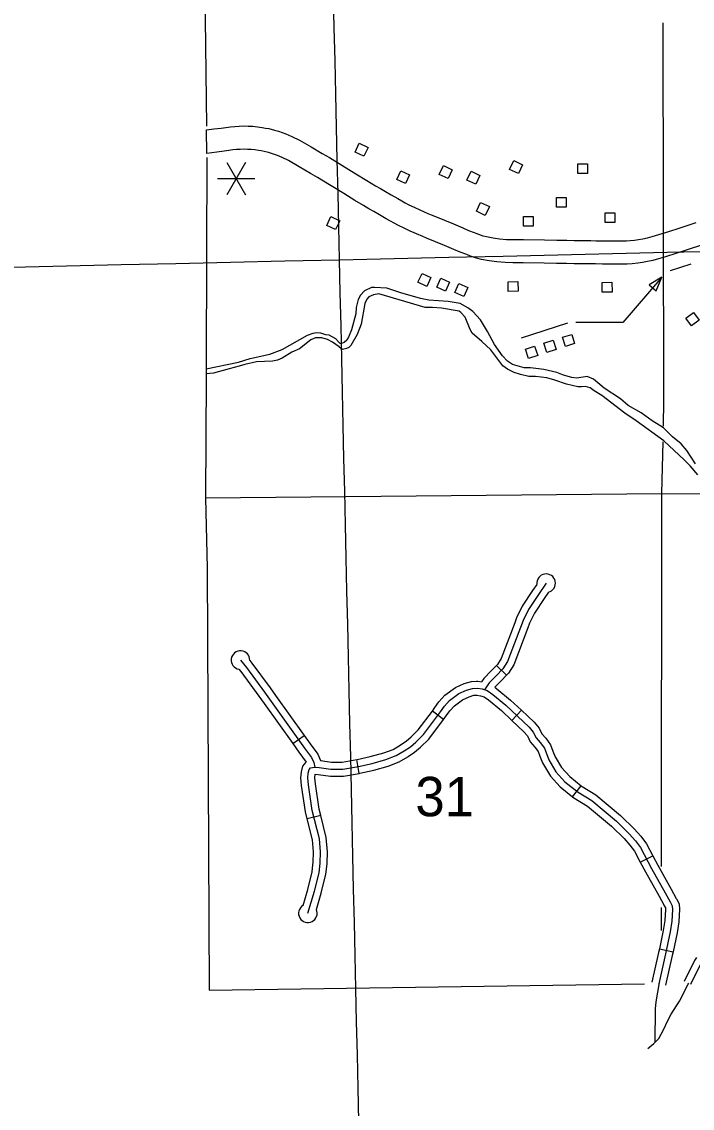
# Model space of a CAD drawing. Extents: x -19 to 366, y -4 to 359.
# Drawn here: x 127.169 to 128.531, y 197.843 to 200.051 of the extents above; entities that cross this region are included whole.
import ezdxf

# ---------------------------------------------------------------- set-up
doc = ezdxf.new("R2010")
doc.units = 0
for name, color, linetype in [('Level 10', 7, 'Continuous'), ('Level 2', 7, 'Continuous'), ('Level 32', 7, 'Continuous'), ('Level 35', 7, 'Continuous'), ('Level 45', 7, 'Continuous'), ('Level 48', 7, 'Continuous'), ('Level 5', 7, 'Continuous'), ('Level 56', 7, 'Continuous'), ('Level 60', 7, 'Continuous')]:
    doc.layers.add(name, color=color, linetype=linetype)

msp = doc.modelspace()

# ---------------------------------------------------------------- linework, layer by layer
at = {"layer": 'Level 10'}
for points in [[(127.5448, 199.7835), (127.5445, 199.8313), (127.5594, 199.8332), (127.5738, 199.8351), (127.5835, 199.8365), (127.5928, 199.8377), (127.6018, 199.8385), (127.6108, 199.839), (127.6203, 199.8393), (127.6291, 199.8391), (127.6383, 199.8388), (127.6482, 199.8378), (127.6576, 199.8365), (127.6639, 199.8352), (127.6711, 199.8339), (127.6828, 199.8311), (127.6907, 199.8287), (127.7055, 199.8236), (127.718, 199.8182), (127.7333, 199.8107), (127.7568, 199.7971), (127.7795, 199.7835), (127.794, 199.7752), (127.819, 199.7599), (127.8477, 199.7424), (127.8702, 199.7287), (127.888, 199.718), (127.8979, 199.712), (127.9077, 199.7065), (127.9195, 199.6996), (127.9328, 199.6918), (127.9414, 199.687), (127.9483, 199.6833), (127.9556, 199.6794), (127.9664, 199.6742), (127.9778, 199.6688), (127.9849, 199.6658), (127.9943, 199.6618), (128.0009, 199.659), (128.0099, 199.6551), (128.0278, 199.6477), (128.0459, 199.6402), (128.0649, 199.6322), (128.077, 199.6272), (128.0881, 199.6229), (128.0918, 199.6215), (128.097, 199.6194), (128.1061, 199.6164), (128.1135, 199.6145), (128.1265, 199.6119), (128.1396, 199.6101), (128.1537, 199.6089), (128.1676, 199.6085), (128.1884, 199.6084), (128.2308, 199.6077), (128.256, 199.6073), (128.2766, 199.607), (128.2917, 199.6069), (128.3117, 199.6065), (128.3253, 199.6064), (128.3355, 199.6062), (128.3494, 199.6059), (128.3651, 199.6058), (128.3764, 199.6057), (128.3869, 199.6057), (128.3976, 199.606), (128.4052, 199.6063), (128.4143, 199.6074), (128.4222, 199.6085), (128.4312, 199.6102), (128.4402, 199.6121), (128.4502, 199.6148), (128.4633, 199.6186), (128.4835, 199.6251), (128.5046, 199.6319), (128.5393, 199.6433)], [(128.554, 199.5982), (128.5192, 199.5869), (128.4981, 199.5801), (128.4771, 199.5733), (128.4629, 199.5692), (128.4514, 199.5661), (128.4405, 199.5638), (128.4299, 199.5618), (128.4205, 199.5604), (128.409, 199.5591), (128.3992, 199.5587), (128.3875, 199.5584), (128.3762, 199.5584), (128.3647, 199.5585), (128.3487, 199.5586), (128.3346, 199.5589), (128.3248, 199.559), (128.3111, 199.5591), (128.2911, 199.5595), (128.2761, 199.5597), (128.2552, 199.56), (128.2301, 199.5604), (128.1879, 199.561), (128.1669, 199.5612), (128.1511, 199.5616), (128.1343, 199.563), (128.1185, 199.5652), (128.103, 199.5683), (128.0926, 199.5709), (128.0807, 199.575), (128.0744, 199.5775), (128.0711, 199.5788), (128.0595, 199.5832), (128.0467, 199.5885), (128.0276, 199.5965), (128.0096, 199.604), (127.9915, 199.6115), (127.9824, 199.6154), (127.9758, 199.6182), (127.9662, 199.6223), (127.9584, 199.6256), (127.946, 199.6314), (127.9343, 199.6372), (127.9259, 199.6415), (127.9185, 199.6456), (127.9093, 199.6507), (127.8957, 199.6587), (127.8842, 199.6654), (127.8741, 199.6711), (127.8635, 199.6775), (127.8456, 199.6882), (127.8231, 199.7019), (127.7943, 199.7195), (127.7698, 199.7344), (127.7555, 199.7427), (127.7328, 199.7563), (127.711, 199.7689), (127.6982, 199.7752), (127.6883, 199.7794), (127.6761, 199.7837), (127.6704, 199.7854), (127.6612, 199.7876), (127.6551, 199.7887), (127.6498, 199.7897), (127.6426, 199.7908), (127.6349, 199.7915), (127.6277, 199.7918), (127.6207, 199.7919), (127.613, 199.7917), (127.6053, 199.7912), (127.5978, 199.7906), (127.5897, 199.7896), (127.5802, 199.7882), (127.5656, 199.7863), (127.5448, 199.7835)]]:
    msp.add_lwpolyline(points, dxfattribs=at)
at = {"layer": 'Level 2'}
for points in [[(127.5449, 200.3115), (127.5416, 200.0569), (127.5444, 199.839)], [(127.5448, 199.7755), (127.5444, 199.5835), (127.5434, 199.3511), (127.5433, 199.3288), (127.5422, 199.084), (127.5454, 198.9405), (127.5498, 198.0835)], [(127.5498, 198.0835), (128.4346, 198.0961)]]:
    msp.add_lwpolyline(points, dxfattribs=at)
at = {"layer": 'Level 32'}
for points in [[(128.8201, 198.5461), (128.8079, 198.5322), (128.7819, 198.5107), (128.765, 198.4923), (128.7451, 198.4693), (128.7282, 198.4417), (128.7022, 198.4065), (128.6754, 198.3666), (128.6578, 198.3398), (128.6501, 198.3153), (128.6432, 198.2823), (128.6356, 198.262), (128.621, 198.239), (128.6003, 198.2115), (128.5712, 198.1731), (128.5483, 198.1364), (128.5275, 198.0947)], [(128.54, 198.1499), (128.5359, 198.1433), (128.5148, 198.101)], [(128.4413, 197.9649), (128.453, 197.9749), (128.4632, 197.9853), (128.4732, 198.0023), (128.4814, 198.0217), (128.4882, 198.0345), (128.5054, 198.061), (128.523, 198.0955), (128.5242, 198.0976)], [(128.4558, 197.9779), (128.4565, 198.0454), (128.4578, 198.0597), (128.4645, 198.0987)]]:
    msp.add_lwpolyline(points, dxfattribs=at)
at = {"layer": 'Level 35'}
for points in [[(128.0595, 199.4787), (128.0356, 199.4824), (127.9962, 199.4852), (127.9788, 199.4887), (127.9389, 199.5002), (127.9104, 199.51), (127.8858, 199.5114), (127.8794, 199.511), (127.8651, 199.5043), (127.8573, 199.4954), (127.8526, 199.4866), (127.8483, 199.4702), (127.8474, 199.4577), (127.8392, 199.4253), (127.8326, 199.4101), (127.8293, 199.4047)], [(128.3064, 199.3091), (128.2988, 199.3093), (128.276, 199.3146), (128.2521, 199.323), (128.2361, 199.3272), (128.213, 199.3303), (128.1991, 199.3304), (128.182, 199.3343), (128.1698, 199.3387), (128.1557, 199.3453), (128.1462, 199.3519), (128.1218, 199.3841), (128.1038, 199.4017), (128.0842, 199.4184), (128.08, 199.4259), (128.0697, 199.4508), (128.0613, 199.4601), (128.0578, 199.4627), (128.0218, 199.4689), (128.0036, 199.4705), (127.9889, 199.4707), (127.8943, 199.4979), (127.8838, 199.4962), (127.8744, 199.4923), (127.8699, 199.4877), (127.8659, 199.4785), (127.8583, 199.4367), (127.8507, 199.4157), (127.8374, 199.3935), (127.8345, 199.39)], [(128.538, 199.1528), (128.5201, 199.1799), (128.5086, 199.1933), (128.491, 199.2078), (128.4729, 199.2257), (128.4496, 199.2401), (128.4274, 199.2561), (128.4011, 199.2716), (128.3854, 199.285), (128.3522, 199.3064), (128.3307, 199.3246), (128.3178, 199.3301), (128.297, 199.3271), (128.2864, 199.3284), (128.2697, 199.3327), (128.256, 199.3386), (128.2298, 199.3446), (128.2026, 199.3479), (128.1897, 199.3481), (128.1661, 199.3549), (128.1562, 199.3616), (128.1458, 199.3724), (128.1296, 199.3953), (128.1152, 199.4219), (128.1008, 199.4456), (128.0854, 199.462), (128.0755, 199.4698), (128.0595, 199.4787)], [(127.5434, 199.3455), (127.6092, 199.3592), (127.6329, 199.3668), (127.6732, 199.3754), (127.698, 199.3853), (127.7497, 199.4142), (127.761, 199.4182), (127.7681, 199.4195), (127.7761, 199.4192), (127.7863, 199.4159), (127.7931, 199.4149), (127.8065, 199.4075), (127.8123, 199.4004)], [(127.814, 199.3902), (127.8002, 199.4002), (127.7899, 199.4054), (127.7789, 199.409), (127.7656, 199.4088), (127.7566, 199.4048), (127.7331, 199.3862), (127.7177, 199.3795), (127.6979, 199.3678), (127.6889, 199.3635), (127.6787, 199.3611), (127.6462, 199.3598), (127.6221, 199.3549), (127.6108, 199.3509), (127.5901, 199.346), (127.5585, 199.3368), (127.5433, 199.3355)], [(127.8123, 199.4004), (127.8153, 199.3977), (127.8179, 199.397), (127.8242, 199.3997), (127.8293, 199.4047)], [(127.814, 199.3902), (127.8209, 199.3861), (127.8295, 199.3875), (127.8345, 199.39)], [(128.5429, 199.1302), (128.5274, 199.1485), (128.5151, 199.1612), (128.4737, 199.1992), (128.4171, 199.2403), (128.3945, 199.2559), (128.3475, 199.2919), (128.3318, 199.3011), (128.3242, 199.3071), (128.3147, 199.3096), (128.3064, 199.3091)]]:
    msp.add_lwpolyline(points, dxfattribs=at)
at = {"layer": 'Level 45'}
for p, q in [((128.1337, 198.7432), (128.154, 198.7234)), ((128.0259, 198.6334), (128.0032, 198.6505)), ((128.1646, 198.6314), (128.1841, 198.6521)), ((127.7195, 198.5843), (127.7426, 198.6008)), ((127.8548, 198.5238), (127.85, 198.5518)), ((128.288, 198.4764), (128.3057, 198.4986)), ((127.7765, 198.4381), (127.7489, 198.4313)), ((128.4258, 198.3433), (128.451, 198.3565)), ((128.4645, 198.1674), (128.4923, 198.1614))]:
    msp.add_line(p, q, dxfattribs=at)
for points in [[(128.2344, 198.9102), (128.2187, 198.8873), (128.1983, 198.8565), (128.1875, 198.8343), (128.1557, 198.7509), (128.1467, 198.7362), (128.1328, 198.7219), (128.1188, 198.7076), (128.1091, 198.6937)], [(128.2156, 198.9079), (128.2069, 198.8953), (128.1859, 198.8636), (128.1745, 198.84), (128.1705, 198.8295)], [(128.239, 198.8918), (128.2304, 198.8794), (128.2106, 198.8495), (128.2006, 198.8287), (128.197, 198.8193)], [(128.1705, 198.8295), (128.1429, 198.7572), (128.1355, 198.745), (128.1337, 198.7432)], [(128.197, 198.8193), (128.1685, 198.7446), (128.158, 198.7275), (128.154, 198.7234)], [(127.6101, 198.7355), (127.6142, 198.7305), (127.6505, 198.6807), (127.6613, 198.6655)], [(127.6133, 198.7541), (127.6255, 198.7391), (127.662, 198.689), (127.7435, 198.5752), (127.7578, 198.5558), (127.7621, 198.5458), (127.7646, 198.5364)], [(127.6322, 198.7533), (127.6367, 198.7478), (127.6735, 198.6973), (127.6844, 198.6821)], [(128.1337, 198.7432), (128.1226, 198.7318), (128.1079, 198.7167), (128.1031, 198.7099)], [(128.154, 198.7234), (128.143, 198.712), (128.13, 198.6987)], [(127.7503, 198.2394), (127.7639, 198.2841), (127.7729, 198.3214), (127.775, 198.3414), (127.7761, 198.3643), (127.7736, 198.3908), (127.7593, 198.4484), (127.7514, 198.5007), (127.7503, 198.515), (127.7511, 198.5243), (127.7528, 198.5315), (127.7557, 198.5347), (127.7636, 198.5365), (127.7729, 198.5358), (127.7972, 198.5322), (127.8215, 198.5326), (127.8534, 198.5379), (127.8806, 198.544), (127.9088, 198.5522), (127.9299, 198.5598), (127.9457, 198.5694), (127.9586, 198.578), (127.9696, 198.5873), (127.985, 198.6027), (128.0197, 198.6489), (128.0276, 198.66), (128.0383, 198.6718), (128.0573, 198.6858), (128.0727, 198.6929), (128.0849, 198.6965), (128.0945, 198.6969), (128.1042, 198.6954), (128.1145, 198.6919), (128.126, 198.6843), (128.1528, 198.6621), (128.1997, 198.6178), (128.2083, 198.6077), (128.214, 198.5959), (128.2226, 198.5863), (128.2308, 198.5752), (128.2398, 198.5512), (128.2544, 198.5268), (128.2727, 198.5068), (128.2992, 198.4857), (128.3271, 198.4688), (128.3772, 198.4266), (128.4033, 198.4012), (128.4158, 198.3869), (128.4262, 198.3733), (128.4487, 198.3303), (128.4763, 198.2813), (128.4863, 198.263), (128.4906, 198.2544), (128.4913, 198.2473), (128.4897, 198.2235), (128.4864, 198.202), (128.4768, 198.1569), (128.4634, 198.0962)], [(128.0032, 198.6505), (128.0083, 198.6573), (128.0165, 198.6689), (128.0288, 198.6824), (128.05, 198.698), (128.0677, 198.7063), (128.0825, 198.7106), (128.0929, 198.711)], [(128.0929, 198.711), (128.0953, 198.7111), (128.1031, 198.7099)], [(128.13, 198.6987), (128.1344, 198.6958), (128.1622, 198.6728), (128.1841, 198.6521)], [(127.6844, 198.6821), (127.7426, 198.6008)], [(128.0259, 198.6334), (128.0312, 198.6405), (128.0387, 198.6511), (128.0479, 198.6612), (128.0646, 198.6735), (128.0777, 198.6796), (128.0872, 198.6824), (128.094, 198.6826)], [(128.0937, 198.6826), (128.1008, 198.6816), (128.1082, 198.679), (128.1175, 198.6729), (128.1434, 198.6515), (128.1646, 198.6314)], [(127.6613, 198.6655), (127.7195, 198.5843)], [(127.9385, 198.5817), (127.95, 198.5894), (127.96, 198.5978), (127.9743, 198.6121), (128.0032, 198.6505)], [(128.1841, 198.6521), (128.21, 198.6276), (128.2203, 198.6156), (128.2259, 198.6039), (128.2336, 198.5952), (128.2434, 198.582), (128.2483, 198.5688)], [(127.9542, 198.5581), (127.9671, 198.5666), (127.9793, 198.5768), (127.9958, 198.5934), (128.0259, 198.6334)], [(128.1646, 198.6314), (128.1894, 198.608), (128.1963, 198.5999), (128.2021, 198.588), (128.2116, 198.5773), (128.2182, 198.5683), (128.2217, 198.5589)], [(127.7195, 198.5843), (127.7321, 198.5668), (127.7471, 198.5464)], [(127.7426, 198.6008), (127.755, 198.5835), (127.7703, 198.5629), (127.7759, 198.5497)], [(127.85, 198.5518), (127.8506, 198.5519), (127.877, 198.5578), (127.9045, 198.5658), (127.9238, 198.5726), (127.938, 198.5814), (127.9385, 198.5817)], [(128.2217, 198.5589), (128.2269, 198.545), (128.243, 198.5183), (128.2629, 198.4964), (128.288, 198.4764)], [(128.2483, 198.5688), (128.2526, 198.5574), (128.2659, 198.5354), (128.2824, 198.5172), (128.3057, 198.4986)], [(127.7489, 198.4313), (127.7453, 198.4457), (127.7373, 198.4991), (127.7361, 198.515), (127.737, 198.5266), (127.7399, 198.5383), (127.7435, 198.5424)], [(127.7435, 198.5424), (127.7471, 198.5464)], [(127.7759, 198.5497), (127.7981, 198.5464), (127.8202, 198.5467), (127.85, 198.5518)], [(127.8548, 198.5238), (127.8561, 198.524), (127.8841, 198.5302), (127.9132, 198.5387), (127.9361, 198.5469), (127.9533, 198.5575), (127.9543, 198.5581)], [(127.7765, 198.4381), (127.7732, 198.4512), (127.7655, 198.5023), (127.7646, 198.515), (127.7651, 198.5221)], [(127.7651, 198.5221), (127.7713, 198.5217), (127.7963, 198.518), (127.8228, 198.5184), (127.8548, 198.5238)], [(128.3057, 198.4986), (128.3073, 198.4973), (128.3354, 198.4804), (128.3855, 198.4381)], [(128.288, 198.4764), (128.291, 198.474), (128.3188, 198.4573), (128.3672, 198.4164)], [(127.7603, 198.3377), (127.7609, 198.3425), (127.7619, 198.364), (127.7596, 198.3884), (127.7489, 198.4313)], [(127.7886, 198.3347), (127.7892, 198.3403), (127.7903, 198.3646), (127.7876, 198.3932), (127.7765, 198.4381)], [(128.3855, 198.4381), (128.3867, 198.4371), (128.4136, 198.411), (128.4268, 198.3959), (128.4382, 198.3809), (128.451, 198.3565)], [(128.3672, 198.4164), (128.3676, 198.4161), (128.393, 198.3914), (128.4048, 198.3779), (128.4141, 198.3656), (128.4258, 198.3433)], [(127.7404, 198.2555), (127.7502, 198.2879), (127.7589, 198.3238), (127.7603, 198.3377)], [(128.4258, 198.3433), (128.4362, 198.3235), (128.4638, 198.2744), (128.4737, 198.2564), (128.4739, 198.256)], [(128.451, 198.3565), (128.4612, 198.3371), (128.4887, 198.2882), (128.4989, 198.2696), (128.4993, 198.2687)], [(127.7676, 198.2472), (127.7776, 198.2804), (127.7869, 198.3189), (127.7886, 198.3347)], [(128.4739, 198.256), (128.4767, 198.2504), (128.477, 198.247), (128.4755, 198.225), (128.4725, 198.2045), (128.4645, 198.1674)], [(128.4993, 198.2687), (128.5044, 198.2584), (128.5055, 198.2475), (128.5038, 198.2219), (128.5004, 198.1994), (128.4923, 198.1614)], [(128.4645, 198.1674), (128.4629, 198.1599), (128.4495, 198.0993)], [(128.4923, 198.1614), (128.4907, 198.1538), (128.4772, 198.0932)]]:
    msp.add_lwpolyline(points, dxfattribs=at)
for centre, start, end in [((128.2344, 198.9102), 284.0967, 186.9158), ((127.6133, 198.7541), 357.5659, 260.3854), ((127.7503, 198.2394), 121.6899, 24.5093)]:
    msp.add_arc(centre, 0.0189, start, end, dxfattribs=at)
at = {"layer": 'Level 48'}
for p, q in [((127.6237, 199.7652), (127.5858, 199.6996)), ((127.5858, 199.7652), (127.6237, 199.6996)), ((127.5668, 199.7324), (127.6426, 199.7324))]:
    msp.add_line(p, q, dxfattribs=at)
at = {"layer": 'Level 5'}
for points in [[(128.4726, 199.2294), (128.4738, 199.2814), (128.4724, 200.0492)], [(128.4695, 199.0922), (128.4719, 199.1976)], [(127.5422, 199.084), (128.4695, 199.0922)], [(128.4688, 198.3346), (128.4695, 199.0922)], [(128.4695, 199.0922), (128.5738, 199.0915)], [(128.4687, 198.2045), (128.4687, 198.2515)]]:
    msp.add_lwpolyline(points, dxfattribs=at)
at = {"layer": 'Level 56'}
for points in [[(127.8462, 199.7864), (127.8547, 199.8042), (127.8725, 199.7956), (127.864, 199.7779)], [(128.0174, 199.741), (128.026, 199.7588), (128.0438, 199.7502), (128.0352, 199.7325)], [(128.1602, 199.7511), (128.1687, 199.7689), (128.1865, 199.7603), (128.178, 199.7426)], [(128.2989, 199.7429), (128.2989, 199.7626), (128.3186, 199.7626), (128.3186, 199.7429)], [(127.9308, 199.7307), (127.9393, 199.7485), (127.9571, 199.7399), (127.9486, 199.7222)], [(128.0736, 199.7294), (128.0821, 199.7472), (128.0999, 199.7386), (128.0914, 199.7209)], [(128.2556, 199.6742), (128.2556, 199.694), (128.2753, 199.694), (128.2753, 199.6742)], [(128.0927, 199.6662), (128.1012, 199.6839), (128.1191, 199.6754), (128.1105, 199.6576)], [(128.3544, 199.6429), (128.3544, 199.6626), (128.3742, 199.6626), (128.3742, 199.6429)], [(127.7887, 199.6373), (127.797, 199.6552), (127.8149, 199.6469), (127.8066, 199.629)], [(128.1881, 199.6358), (128.1881, 199.6555), (128.2079, 199.6555), (128.2079, 199.6358)], [(127.9919, 199.5134), (127.974, 199.5216), (127.9822, 199.5396), (128.0001, 199.5314)], [(128.0301, 199.5038), (128.0122, 199.512), (128.0204, 199.53), (128.0383, 199.5218)], [(128.4436, 199.5167), (128.4582, 199.5041), (128.4698, 199.5324)], [(128.0671, 199.493), (128.0491, 199.5012), (128.0573, 199.5191), (128.0753, 199.511)], [(128.1773, 199.5034), (128.1576, 199.503), (128.1572, 199.5228), (128.177, 199.5231)], [(128.3683, 199.5018), (128.3486, 199.5014), (128.3482, 199.5212), (128.3679, 199.5216)], [(128.5456, 199.4446), (128.5297, 199.4329), (128.518, 199.4488), (128.5338, 199.4605)], [(128.2358, 199.3791), (128.2298, 199.3979), (128.2487, 199.4039), (128.2546, 199.3851)], [(128.2735, 199.3911), (128.2675, 199.4099), (128.2863, 199.4159), (128.2923, 199.3971)], [(128.2174, 199.3732), (128.1987, 199.3668), (128.1923, 199.3855), (128.211, 199.3919)]]:
    msp.add_lwpolyline(points, close=True, dxfattribs=at)
for points in [[(128.4872, 199.5457), (128.5293, 199.5594)], [(128.4698, 199.5324), (128.3901, 199.4397), (128.2946, 199.4397)], [(128.1847, 199.4091), (128.2787, 199.4395)]]:
    msp.add_lwpolyline(points, dxfattribs=at)
at = {"layer": 'Level 60'}
for points in [[(132.1027, 1.3746), (131.9232, 9.99), (131.7429, 18.6056), (131.5621, 27.2214), (131.3806, 35.8373), (131.1985, 44.4533), (131.0158, 53.0695), (130.8324, 61.6859), (130.6485, 70.3024), (130.4639, 78.919), (130.2786, 87.5358), (130.0928, 96.1527), (129.9063, 104.7698), (129.7193, 113.387), (129.5316, 122.0044), (129.3433, 130.6219), (129.1543, 139.2396), (128.9648, 147.8575), (128.7746, 156.4754), (128.5838, 165.0936), (128.3925, 173.7119), (128.2005, 182.3303), (128.0078, 190.9489), (127.8146, 199.5676), (127.6208, 208.1865), (127.4264, 216.8056), (127.2313, 225.4247), (127.0357, 234.0441), (126.8394, 242.6636), (126.6425, 251.2833), (126.4451, 259.9031), (126.247, 268.523), (126.0483, 277.1431), (125.849, 285.7634), (125.6492, 294.3838), (125.4487, 303.0044), (125.2476, 311.6252), (125.0459, 320.2461), (124.8437, 328.8671), (124.6408, 337.4883), (124.4373, 346.1097)], [(0, 198.1326), (7.1014, 198.137), (14.2028, 198.1503), (21.3042, 198.1724), (28.4055, 198.2034), (35.5068, 198.2433), (42.6081, 198.292), (49.7092, 198.3496), (56.8103, 198.4161), (63.9113, 198.4913), (71.0123, 198.5755), (78.1131, 198.6685), (85.2137, 198.7704), (92.3143, 198.8811), (99.4147, 199.0007), (106.5149, 199.1291), (113.615, 199.2664), (120.7149, 199.4126), (127.8146, 199.5676), (134.9141, 199.7315), (142.0135, 199.9042), (149.1125, 200.0858), (156.2114, 200.2762), (163.31, 200.4755), (170.4084, 200.6837), (177.5065, 200.9007), (184.6043, 201.1265), (191.7018, 201.3612), (198.799, 201.6048), (205.896, 201.8572), (212.9926, 202.1185), (220.0888, 202.3886), (227.1848, 202.6676), (234.2803, 202.9554), (241.3755, 203.2521), (248.4704, 203.5576), (255.5648, 203.872), (262.6589, 204.1952), (269.7525, 204.5273), (276.8457, 204.8682), (283.9385, 205.218), (291.0309, 205.5766), (298.1228, 205.9441), (305.2142, 206.3204), (312.3051, 206.7056), (319.3956, 207.0996), (326.4856, 207.5024), (333.5751, 207.9141), (340.664, 208.3347)], [(0, 189.5162), (7.1121, 189.5206), (14.2243, 189.5339), (21.3364, 189.556), (28.4484, 189.5869), (35.5605, 189.6267), (42.6725, 189.6754), (49.7844, 189.7329), (56.8962, 189.7992), (64.0079, 189.8744), (71.1196, 189.9584), (78.2311, 190.0512), (85.3425, 190.1529), (92.4538, 190.2635), (99.5649, 190.3829), (106.6759, 190.5111), (113.7867, 190.6482), (120.8974, 190.7941), (128.0078, 190.9489), (135.1181, 191.1125), (142.2282, 191.2849), (149.338, 191.4662), (156.4476, 191.6563), (163.5569, 191.8553), (170.666, 192.0631), (177.7749, 192.2798), (184.8835, 192.5053), (191.9917, 192.7396), (199.0997, 192.9828), (206.2074, 193.2348), (213.3147, 193.4956), (220.4218, 193.7653), (227.5285, 194.0438), (234.6348, 194.3312), (241.7408, 194.6274), (248.8464, 194.9324), (255.9516, 195.2463), (263.0564, 195.569), (270.1608, 195.9005), (277.2648, 196.2409), (284.3683, 196.5901), (291.4715, 196.9481), (298.5741, 197.315), (305.6763, 197.6907), (312.7781, 198.0753), (319.8793, 198.4686), (326.9801, 198.8708), (334.0804, 199.2818), (341.1801, 199.7017)]]:
    msp.add_spline(points, degree=3, dxfattribs=at)

# ---------------------------------------------------------------- texts
at = {"layer": 'Level 5'}
msp.add_text('31', height=0.08, dxfattribs=at).set_placement((127.9688, 198.4366))

doc.saveas('drawing.dxf')
